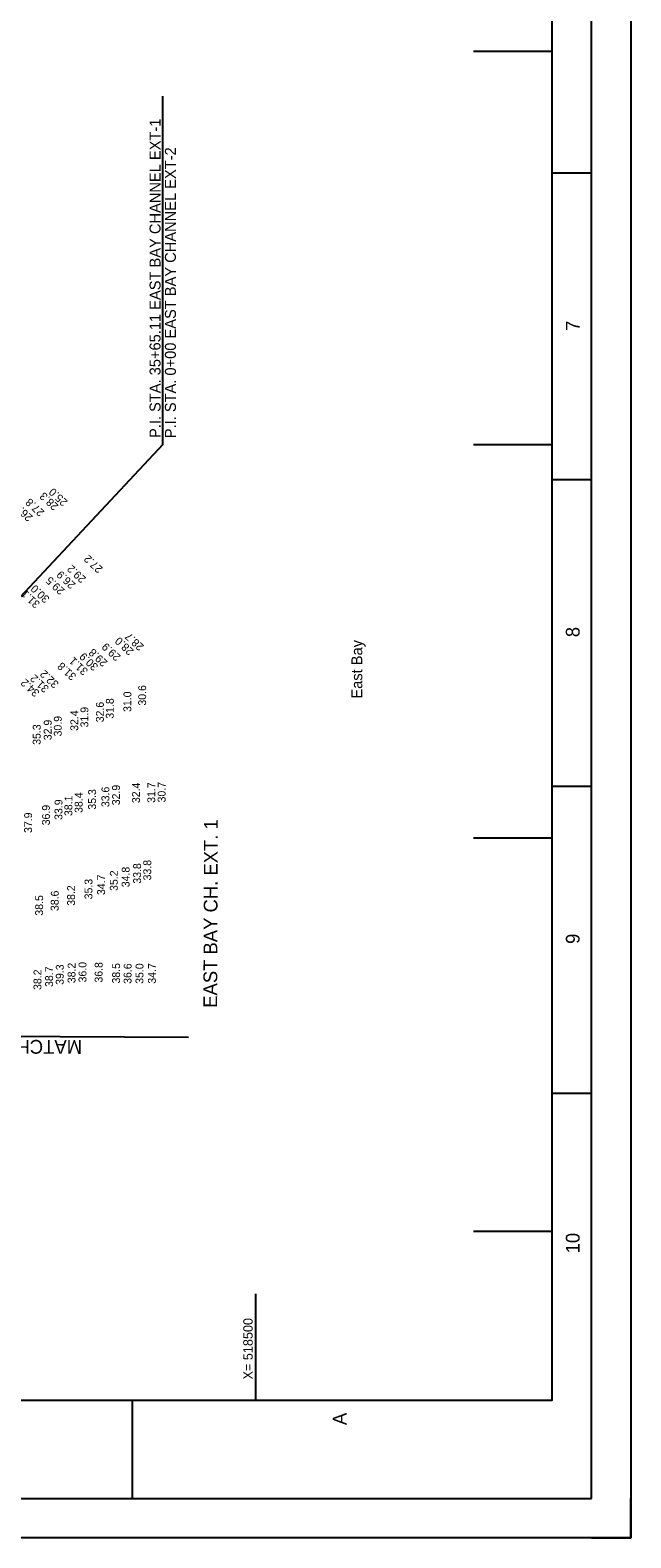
# Model space of a CAD drawing. Extents: x 515576 to 518976, y 1305110 to 1309511.
# Drawn here: x 518213 to 518976, y 1305110 to 1307027 of the extents above; entities that cross this region are included whole.
import ezdxf

# ---------------------------------------------------------------- set-up
doc = ezdxf.new("R2010")
doc.units = 0
for name, color, linetype in [('G-ANNO-NPLT', 7, 'Continuous'), ('G-ANNO-TTLB', 7, 'Continuous'), ('V-ALGN-TEXT', 7, 'Continuous'), ('V-ANNO-MATC', 7, 'Continuous'), ('V-ANNO-MATC-IDEN', 7, 'Continuous'), ('V-CHAN-CNTR-IDEN', 7, 'Continuous'), ('V-SITE-WATR', 7, 'Continuous'), ('V-TOPO-COOR-STAT', 7, 'Continuous'), ('V-TOPO-SOUN', 7, 'Continuous')]:
    doc.layers.add(name, color=color, linetype=linetype)

msp = doc.modelspace()

# ---------------------------------------------------------------- linework, layer by layer
at = {"layer": 'G-ANNO-NPLT'}
msp.add_lwpolyline([(515576.5, 1305110.5), (515576.5, 1309510.4), (518976.4, 1309510.4), (518976.4, 1305110.5)], close=True, dxfattribs=at)
msp.add_lwpolyline([(518926.4, 1305110.5), (518976.4, 1305110.5), (518976.4, 1305160.5)], dxfattribs=at)
at = {"layer": 'G-ANNO-TTLB'}
for p, q in [((518926.4, 1306845.4), (518876.4, 1306845.4)), ((518926.4, 1306455.4), (518876.4, 1306455.4)), ((518926.4, 1306065.4), (518876.4, 1306065.4)), ((518926.4, 1305675.5), (518876.4, 1305675.5)), ((518343.1, 1305160.5), (518343.1, 1305285.5))]:
    msp.add_line(p, q, dxfattribs=at)
for points in [[(518926.4, 1305160.5), (518926.4, 1309460.4), (515626.5, 1309460.4), (515626.5, 1305160.5)], [(515676.5, 1309410.4), (515676.5, 1305285.5), (518876.4, 1305285.5), (518876.4, 1309410.4)]]:
    msp.add_lwpolyline(points, close=True, dxfattribs=at)
at = {"layer": 'V-ALGN-TEXT'}
for q in [(518381.7, 1306943.3), (518020.6, 1306113.7)]:
    msp.add_line((518381.7, 1306500.4), q, dxfattribs=at)
at = {"layer": 'V-ANNO-MATC'}
msp.add_line((517669.2, 1305749.9), (518414.5, 1305747.1), dxfattribs=at)
at = {"layer": 'V-TOPO-COOR-STAT'}
for p, q in [((518876.4, 1307000), (518776.4, 1307000)), ((518876.4, 1306500), (518776.4, 1306500)), ((518876.4, 1306000), (518776.4, 1306000)), ((518876.4, 1305500), (518776.4, 1305500)), ((518500, 1305285.5), (518500, 1305420.5))]:
    msp.add_line(p, q, dxfattribs=at)

# ---------------------------------------------------------------- texts
at = {"layer": 'G-ANNO-TTLB'}
for s, p in [('7', (518911.4, 1306644.8)), ('8', (518911.4, 1306255.4)), ('9', (518911.4, 1305865.5)), ('10', (518911.4, 1305472.1)), ('A', (518615.2, 1305253.8))]:
    msp.add_text(s, height=17.5, rotation=90, dxfattribs=at).set_placement(p)
at = {"layer": 'V-ALGN-TEXT'}
for s, p in [('P.I. STA. 35+65.11 EAST BAY CHANNEL EXT-1', (518378.9, 1306508.6)), ('P.I. STA. 0+00 EAST BAY CHANNEL EXT-2', (518398.4, 1306508.3))]:
    msp.add_text(s, height=13.92, rotation=90, dxfattribs=at).set_placement(p)
at = {"layer": 'V-ANNO-MATC-IDEN'}
msp.add_text('MATCHLINE SHEET NO. 14 STA. 32+00', height=17.52, rotation=179.7829, dxfattribs=at).set_placement((518279.2, 1305743.2))
at = {"layer": 'V-CHAN-CNTR-IDEN'}
msp.add_text('EAST BAY CH. EXT. 1', height=17.52, rotation=89.7829, dxfattribs=at).set_placement((518450.8, 1305784.3))
at = {"layer": 'V-SITE-WATR'}
msp.add_text('East Bay', height=13.92, rotation=90, dxfattribs=at).set_placement((518635.3, 1306177.3))
at = {"layer": 'V-TOPO-COOR-STAT'}
msp.add_text('X= 518500', height=12, rotation=90, dxfattribs=at).set_placement((518496, 1305311.8))
at = {"layer": 'V-TOPO-SOUN'}
for s, rotation, p in [('25.0 ', 136.9626, (518261.7, 1306428.1)), ('26.4 ', 136.9626, (518217.3, 1306408.7)), ('27.8 ', 136.9626, (518232.1, 1306415)), ('28.3 ', 136.9626, (518250.1, 1306422.7)), ('29.2 ', 136.9626, (518285, 1306330.5)), ('27.2 ', 136.9626, (518306.3, 1306343.1)), ('29.5 ', 136.9626, (518257.9, 1306315.5)), ('26.9 ', 136.9626, (518271.6, 1306323)), ('31.1 ', 136.9626, (518226.6, 1306298.5)), ('30.0 ', 136.9626, (518238.7, 1306305.1)), ('28.0 ', 136.9626, (518345.7, 1306238.6)), ('28.7 ', 136.9626, (518358.6, 1306244.3)), ('30.9 ', 136.9626, (518300.6, 1306218.9)), ('29.8 ', 136.9626, (518312.4, 1306224)), ('29.9 ', 136.9626, (518329, 1306231.3)), ('32.2 ', 136.9626, (518250.5, 1306196.8)), ('31.8 ', 136.9626, (518272.7, 1306206.6)), ('31.1 ', 136.9626, (518287.6, 1306213.2)), ('34.2 ', 136.9626, (518226, 1306185.7)), ('31.2 ', 136.9626, (518238, 1306191.1)), ('30.6 ', 89.7825, (518360.5, 1306168.4)), ('31.8 ', 89.7825, (518319.4, 1306151.7)), ('31.0 ', 89.7825, (518341.7, 1306160.3)), ('30.9 ', 89.7825, (518253.3, 1306129.2)), ('32.4 ', 89.7825, (518274.3, 1306136.3)), ('31.9 ', 89.7825, (518287.1, 1306140.7)), ('32.6 ', 89.7825, (518306.8, 1306147.2)), ('35.3 ', 89.7825, (518226.5, 1306118.5)), ('32.9 ', 89.7825, (518240.5, 1306124.4)), ('35.3 ', 89.7825, (518296.9, 1306036.1)), ('33.6 ', 89.7825, (518313.8, 1306039.3)), ('32.9 ', 89.7825, (518327.3, 1306041.7)), ('32.4 ', 89.7825, (518352.7, 1306044.4)), ('31.7 ', 89.7825, (518372.1, 1306044.8)), ('30.7 ', 89.7825, (518385.3, 1306045.3)), ('36.9 ', 89.7825, (518238.3, 1306016.2)), ('33.9 ', 89.7825, (518254.2, 1306023.1)), ('38.1 ', 89.7825, (518266.8, 1306028)), ('38.4 ', 89.7825, (518279.8, 1306032)), ('37.9 ', 89.7825, (518215.6, 1306006.5)), ('34.8 ', 89.7825, (518339.5, 1305937.5)), ('33.8 ', 89.7825, (518354.1, 1305942)), ('33.8 ', 89.7825, (518367, 1305946.2)), ('35.3 ', 89.7825, (518292.3, 1305922.1)), ('34.7 ', 89.7825, (518308.4, 1305927.5)), ('35.2 ', 89.7825, (518324.5, 1305932.8)), ('38.5 ', 89.7825, (518229.6, 1305901.4)), ('38.6 ', 89.7825, (518249.4, 1305907.2)), ('38.2 ', 89.7825, (518270.2, 1305913.9)), ('38.2 ', 89.7825, (518227.5, 1305806.9)), ('38.7 ', 89.7825, (518242.3, 1305810.7)), ('39.3 ', 89.7825, (518255.8, 1305813.4)), ('38.2 ', 89.7825, (518270.8, 1305815.5)), ('36.0 ', 89.7825, (518284.7, 1305816.5)), ('36.8 ', 89.7825, (518305.2, 1305816.3)), ('38.5 ', 89.7825, (518327.4, 1305815.1)), ('36.6 ', 89.7825, (518342, 1305814.7)), ('35.0 ', 89.7825, (518357.1, 1305814.7)), ('34.7 ', 89.7825, (518372.9, 1305814.9))]:
    msp.add_text(s, height=10, rotation=rotation, dxfattribs=at).set_placement(p)

doc.saveas('drawing.dxf')
